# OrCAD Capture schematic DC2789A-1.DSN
size A
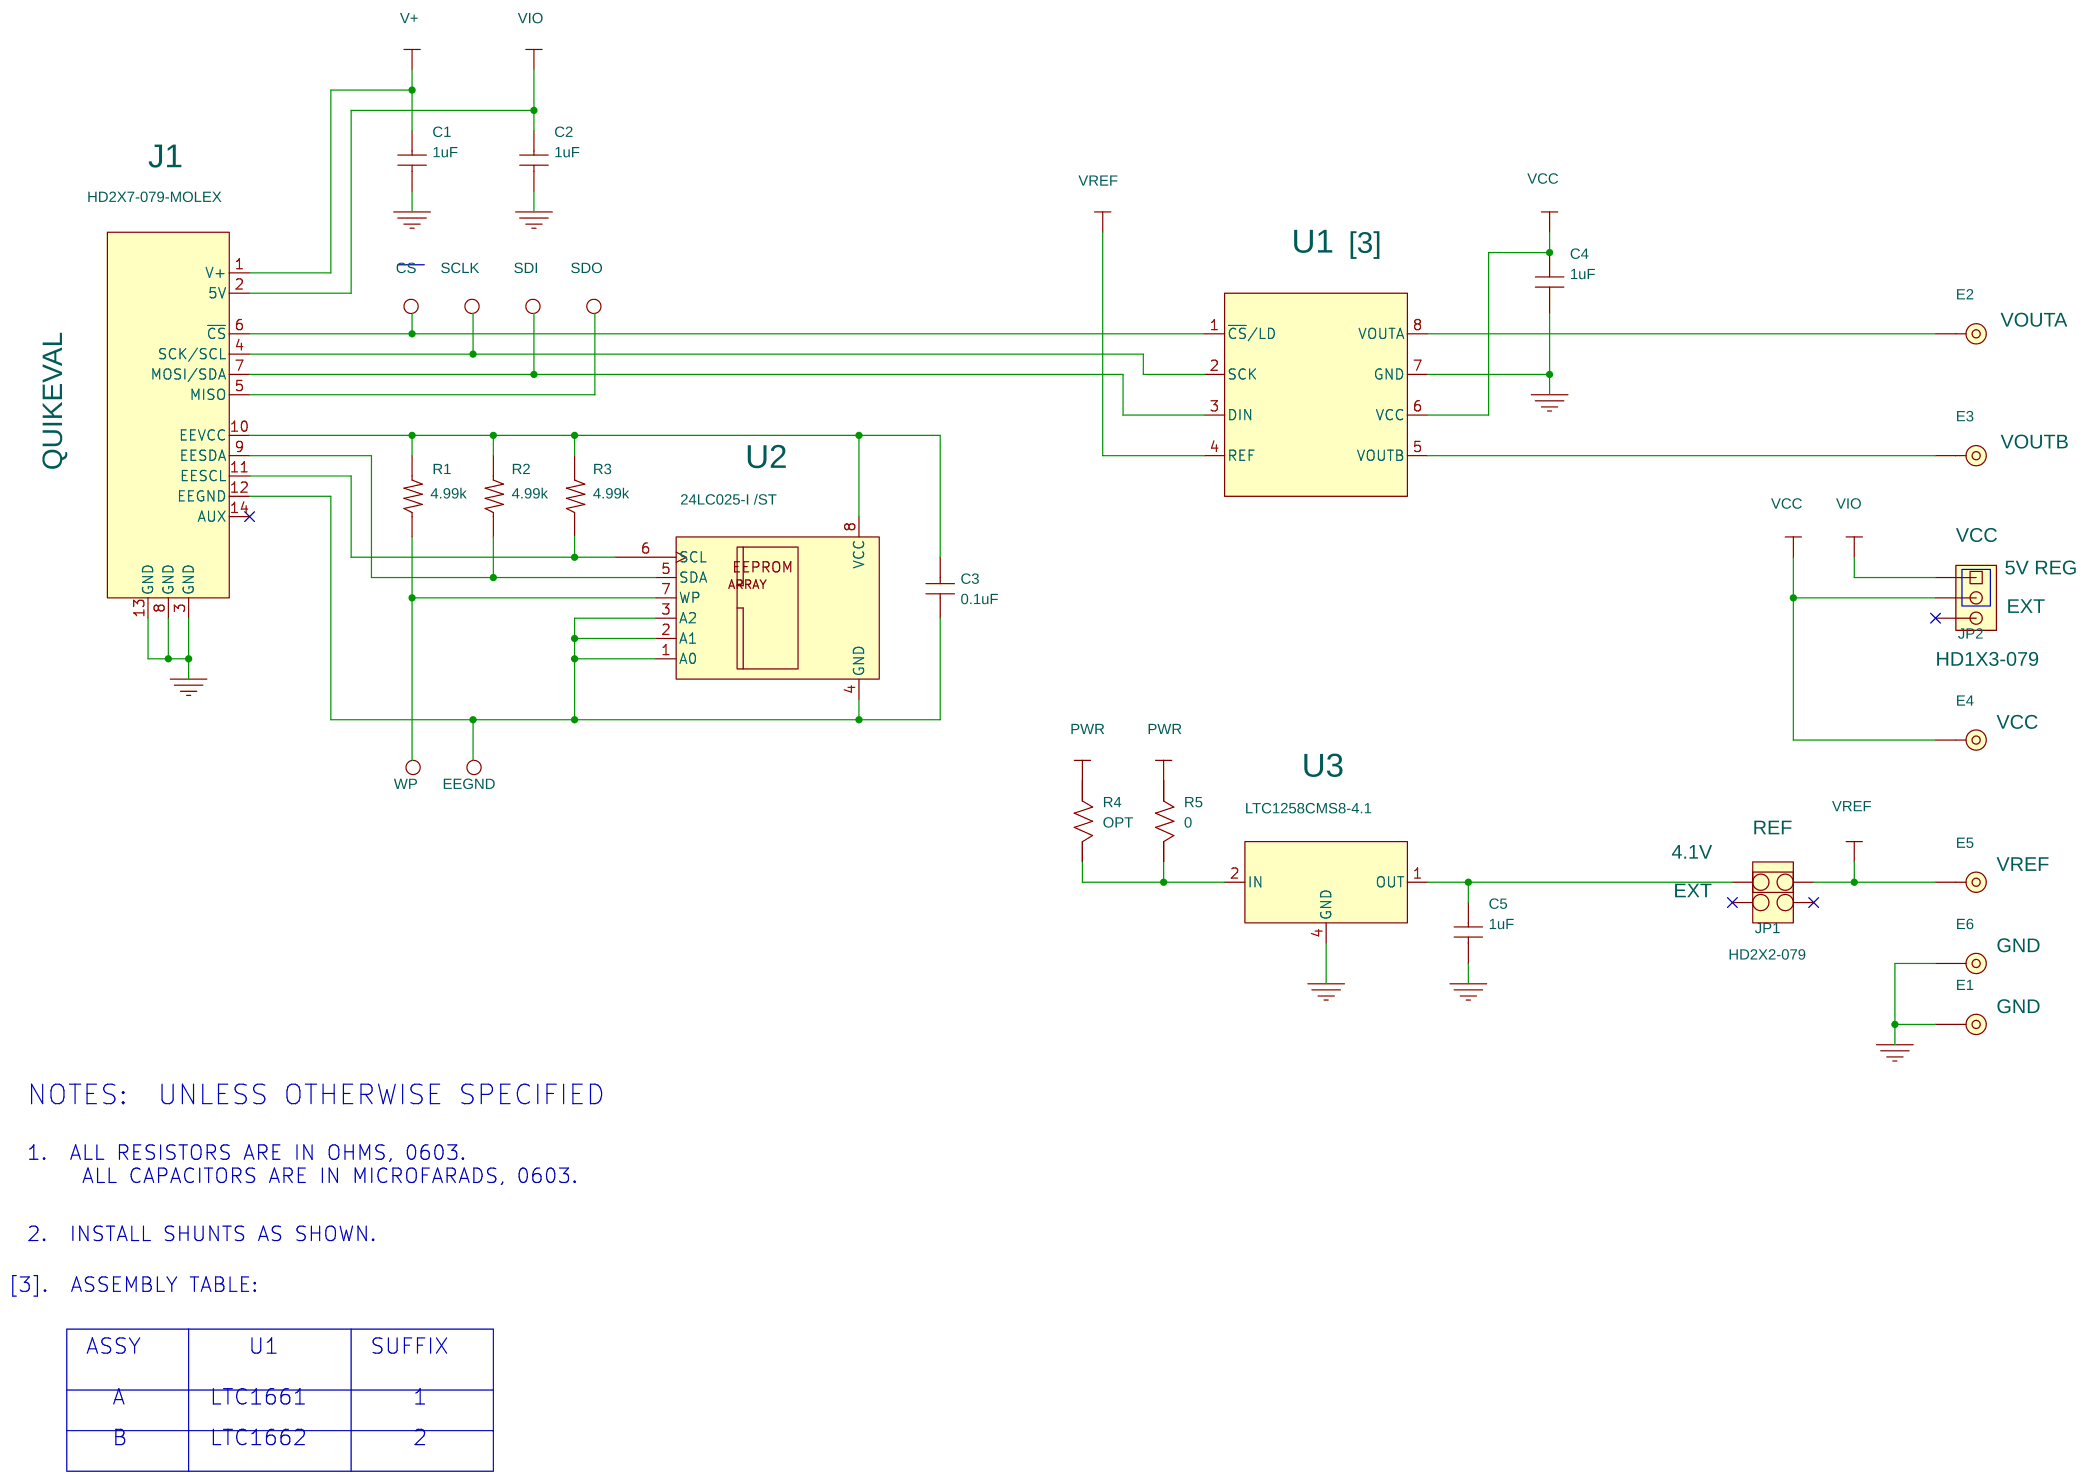
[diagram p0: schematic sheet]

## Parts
C1  1uF  [0603]
C2  1uF  [0603]
C3  0.1uF  [0603]
C4  1uF  [0603]
C5  1uF  [0603]
CS  PAD060-035  [PAD060-035]
E1  PAD120-064  [PAD120-064]
E2  PAD120-064  [PAD120-064]
E3  PAD120-064  [PAD120-064]
E4  PAD120-064  [PAD120-064]
E5  PAD120-064  [PAD120-064]
E6  PAD120-064  [PAD120-064]
EEGND  PAD060-035  [PAD060-035]
J1  HD2X7-079-MOLEX  [HD2X7-079-MOLEX]
JP1  HD2X2-079  [HD2X2-079]
JP2  HD1X3-079  [HD1X3-079]
R1  4.99k  [0603]
R2  4.99k  [0603]
R3  4.99k  [0603]
R4  OPT  [0603]
R5  0  [0603]
SCLK  PAD060-035  [PAD060-035]
SDI  PAD060-035  [PAD060-035]
SDO  PAD060-035  [PAD060-035]
U1  [3]  [MS8]
U2  24LC025-I /ST  [TSSOP8]
U3  LTC1258CMS8-4.1  [MS8]
WP  PAD060-035  [PAD060-035]

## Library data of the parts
C1-C5 = CAP-NP
CS EEGND SCLK SDI SDO WP = E-060-035
E1 E6 = E-064_0: COMPFIXED: GND
E2 = E-064_0: COMPFIXED: VOUTA
E3 = E-064_0: COMPFIXED: VOUTB
E4 = E-064_0: COMPFIXED: VCC
E5 = E-064_0: COMPFIXED: VREF
J1 = HD2X7-079-MOLEX: 1ST PART FIELD: QUIKEVAL
JP1 = HD2X2-079_0: 1ST PART FIELD: REF; 2ND PART FIELD: EXT; 3RD PART FIELD: 4.1V
JP2 = HD1X3: COMPFIXED: VCC; COMPGROUP: 5V REG; COMPKEY: EXT
R1-R3 = R
R4 R5 = R-SMALL
U1 = LTC1661IMS8-MS8
U2 = 24LC025-I_ST
U3 = LTC1258CMS8-4.1-MS8

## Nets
GND: C1.2 C2.2 C4.2 C5.2 E1.1(A) E6.1(A) J1.3(GND) J1.8(GND) J1.13(GND) U1.7(GND) U3.4(GND)
VCC: C4.1 E4.1(A) JP2.2 U1.6(VCC)
V+: C1.1 J1.1(V+) R4.2
VIO: C2.1 J1.2(5V) JP2.1 R5.2
VREF: E5.1(A) JP1.2 U1.4(REF)
N16430992: R4.1 R5.1 U3.2(IN)
N16431226: C5.1 JP1.1 U3.1(OUT)
N16726328: CS.1 J1.6(~{CS}) U1.1(~{CS}/LD)
N16726332: J1.4(SCK/SCL) SCLK.1 U1.2(SCK)
N16726336: J1.7(MOSI/SDA) SDI.1 U1.3(DIN)
N16726340: J1.5(MISO) SDO.1
N16726384: C3.2 J1.10(EEVCC) R1.2 R2.2 R3.2 U2.8(VCC)
N16726424: J1.9(EESDA) R2.1 U2.5(SDA)
N16726432: J1.11(EESCL) R3.1 U2.6(SCL)
N16726488: C3.1 EEGND.1 J1.12(EEGND) U2.1(A0) U2.2(A1) U2.3(A2) U2.4(GND)
N16726524: R1.1 U2.7(WP) WP.1
N16735547: E2.1(A) U1.8(VOUTA)
N16735577: E3.1(A) U1.5(VOUTB)

Not connected (* = marked no-connect by the designer): J1 14(AUX)*; JP1 3* 4*; JP2 3*

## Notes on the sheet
- NOTES:  UNLESS OTHERWISE SPECIFIED
- 1.  ALL RESISTORS ARE IN OHMS, 0603.
       ALL CAPACITORS ARE IN MICROFARADS, 0603.
- 2.  INSTALL SHUNTS AS SHOWN.
- [3].  ASSEMBLY TABLE:
- ASSY
- U1
- SUFFIX
- A
- LTC1661
- 1
- B
- LTC1662
- 2
